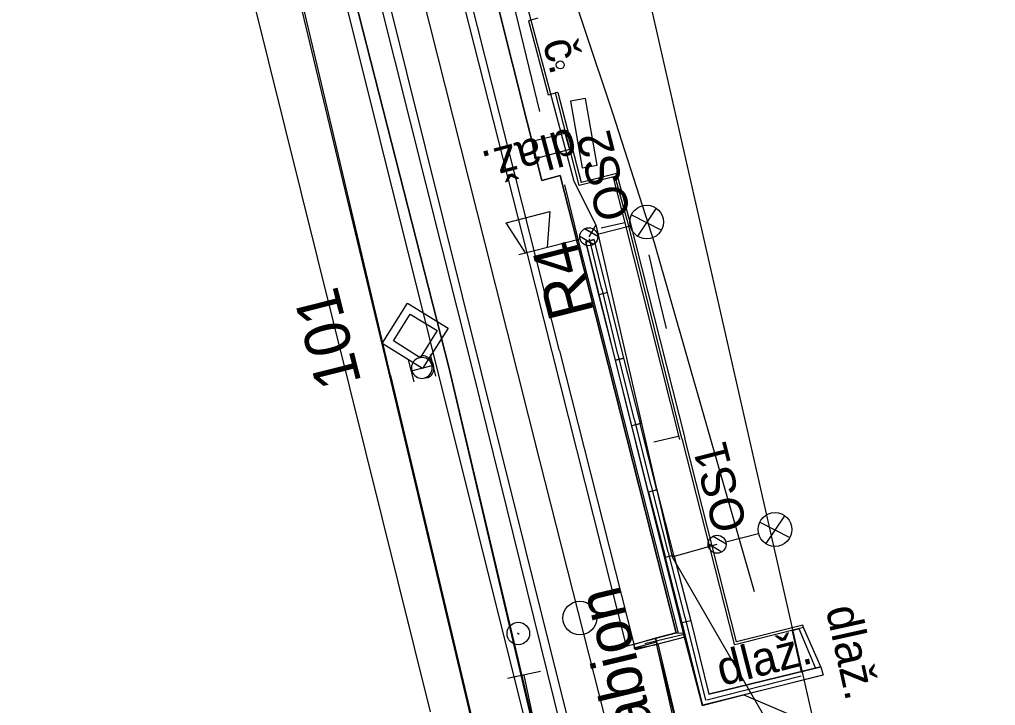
# Model space of a CAD drawing. Extents: x -754679 to -754173, y -1169241 to -1168288.
# Drawn here: x -754414.28 to -754371, y -1168944.54 to -1168914.1 of the extents above; entities that cross this region are included whole.
import ezdxf

# ---------------------------------------------------------------- set-up
doc = ezdxf.new("R2010")
doc.units = 0
for name, color, linetype in [('Vrstva 1', 7, 'Continuous'), ('Vrstva 11', 7, 'Continuous'), ('Vrstva 12', 7, 'Continuous'), ('Vrstva 13', 7, 'Continuous'), ('Vrstva 14', 7, 'Continuous'), ('Vrstva 16', 7, 'Continuous'), ('Vrstva 17', 7, 'Continuous'), ('Vrstva 23', 7, 'Continuous'), ('Vrstva 25', 7, 'Continuous'), ('Vrstva 31', 7, 'Continuous'), ('Vrstva 33', 7, 'Continuous'), ('Vrstva 4', 7, 'Continuous'), ('Vrstva 43', 7, 'Continuous'), ('Vrstva 49', 7, 'Continuous'), ('Vrstva 51', 7, 'Continuous'), ('Vrstva 53', 7, 'Continuous'), ('Vrstva 59', 7, 'Continuous'), ('Vrstva 6', 7, 'Continuous'), ('Vrstva 63', 7, 'Continuous'), ('Vrstva 7', 7, 'Continuous')]:
    doc.layers.add(name, color=color, linetype=linetype)

msp = doc.modelspace()

# ---------------------------------------------------------------- linework, layer by layer
at = {"layer": 'Vrstva 1'}
msp.add_lwpolyline([(-754384.656, -1168959.571), (-754385.936, -1168954.491), (-754386.734, -1168951.322), (-754387.865, -1168946.893), (-754387.928, -1168946.598), (-754389.016, -1168942.293), (-754391.2, -1168933.67), (-754393.647, -1168923.979), (-754396.084, -1168914.315), (-754398.294, -1168905.574)], dxfattribs=at)
at = {"layer": 'Vrstva 11'}
for p, q in [((-754396.779, -1168930.169), (-754397.024, -1168929.2)), ((-754395.81, -1168929.924), (-754396.055, -1168928.955)), ((-754396.902, -1168929.685), (-754395.932, -1168929.439))]:
    msp.add_line(p, q, dxfattribs=at)
at = {"layer": 'Vrstva 12'}
for p, q in [((-754396.521, -1168929.047), (-754396.519, -1168929.099)), ((-754395.985, -1168929.451), (-754395.912, -1168929.468)), ((-754396.315, -1168930.002), (-754396.285, -1168929.991))]:
    msp.add_line(p, q, dxfattribs=at)
for centre, major_axis, ratio, start_param, end_param in [((-754396.437, -1168929.555), (-0.102, 0.452), 0.999997, 6.240007, 10.999586), ((-754396.328, -1168929.506), (-0.199, 0.457), 0.826527, 2.759103, 6.267517), ((-754396.437, -1168929.555), (-0.102, 0.452), 0.999997, 3.184771, 6.240007)]:
    msp.add_ellipse(centre, major_axis=major_axis, ratio=ratio, start_param=start_param, end_param=end_param, dxfattribs=at)
at = {"layer": 'Vrstva 13'}
for p, q in [((-754388.795, -1168923.864), (-754389.165, -1168923.968)), ((-754388.582, -1168926.306), (-754389.165, -1168923.968)), ((-754389.165, -1168923.968), (-754389.161, -1168923.973)), ((-754389.161, -1168923.973), (-754388.795, -1168923.864)), ((-754389.161, -1168923.973), (-754386.419, -1168935.058)), ((-754388.209, -1168926.212), (-754388.795, -1168923.864)), ((-754388.795, -1168923.864), (-754388.795, -1168923.864)), ((-754388.209, -1168926.212), (-754388.582, -1168926.306)), ((-754388.207, -1168926.214), (-754388.582, -1168926.307)), ((-754388.582, -1168926.307), (-754388.582, -1168926.306)), ((-754387.853, -1168929.212), (-754388.582, -1168926.307)), ((-754388.207, -1168926.214), (-754388.209, -1168926.212)), ((-754387.475, -1168929.122), (-754388.207, -1168926.214)), ((-754387.475, -1168929.122), (-754387.853, -1168929.212)), ((-754387.853, -1168929.212), (-754387.481, -1168929.123)), ((-754387.123, -1168932.124), (-754387.853, -1168929.212)), ((-754387.853, -1168929.212), (-754387.853, -1168929.212)), ((-754387.481, -1168929.123), (-754387.475, -1168929.122)), ((-754386.748, -1168932.026), (-754387.481, -1168929.123)), ((-754386.748, -1168932.026), (-754387.123, -1168932.124)), ((-754387.122, -1168932.123), (-754387.123, -1168932.124)), ((-754386.75, -1168932.032), (-754387.122, -1168932.123)), ((-754386.387, -1168935.069), (-754387.122, -1168932.123)), ((-754386.75, -1168932.032), (-754386.748, -1168932.026)), ((-754386.01, -1168934.971), (-754386.75, -1168932.032)), ((-754386.419, -1168935.058), (-754384.844, -1168941.33)), ((-754386.009, -1168934.97), (-754386.387, -1168935.07)), ((-754386.01, -1168934.971), (-754386.387, -1168935.069)), ((-754386.387, -1168935.07), (-754386.387, -1168935.069)), ((-754386.387, -1168935.07), (-754385.634, -1168937.967)), ((-754386.009, -1168934.97), (-754386.01, -1168934.971)), ((-754385.256, -1168937.865), (-754386.009, -1168934.97)), ((-754385.256, -1168937.865), (-754385.634, -1168937.967)), ((-754385.256, -1168937.866), (-754385.631, -1168937.968)), ((-754385.256, -1168937.866), (-754385.256, -1168937.865)), ((-754385.256, -1168937.866), (-754384.511, -1168940.778)), ((-754385.631, -1168937.968), (-754385.634, -1168937.967)), ((-754384.889, -1168940.869), (-754385.631, -1168937.968)), ((-754384.51, -1168940.78), (-754384.892, -1168940.869)), ((-754383.981, -1168944.518), (-754384.892, -1168940.869)), ((-754384.892, -1168940.869), (-754384.889, -1168940.869)), ((-754384.511, -1168940.778), (-754384.889, -1168940.869)), ((-754384.51, -1168940.78), (-754384.511, -1168940.778)), ((-754384.511, -1168940.778), (-754383.714, -1168944.039)), ((-754384.51, -1168940.78), (-754383.714, -1168944.04)), ((-754384.844, -1168941.33), (-754384.011, -1168944.533)), ((-754386.071, -1168941.545), (-754387.015, -1168941.827)), ((-754386.027, -1168941.732), (-754386.979, -1168941.973)), ((-754386.008, -1168941.815), (-754386.071, -1168941.545)), ((-754386.027, -1168941.731), (-754386.027, -1168941.732)), ((-754386.007, -1168941.817), (-754386.027, -1168941.732)), ((-754385.963, -1168941.8), (-754384.759, -1168941.493)), ((-754384.759, -1168941.493), (-754384.006, -1168944.538)), ((-754386.97, -1168942.062), (-754387.015, -1168941.827)), ((-754386.96, -1168942.06), (-754386.979, -1168941.973)), ((-754386.008, -1168941.815), (-754386.97, -1168942.062)), ((-754386.023, -1168941.847), (-754385.963, -1168941.8)), ((-754385.064, -1168945.684), (-754386.023, -1168941.847)), ((-754386.008, -1168941.815), (-754386.007, -1168941.817)), ((-754385.032, -1168945.69), (-754385.963, -1168941.8)), ((-754383.714, -1168944.039), (-754378.74, -1168942.822)), ((-754378.748, -1168942.827), (-754383.714, -1168944.04)), ((-754378.748, -1168942.827), (-754378.74, -1168942.822)), ((-754378.748, -1168942.827), (-754378.643, -1168943.195)), ((-754378.65, -1168943.193), (-754384.011, -1168944.533)), ((-754378.643, -1168943.195), (-754383.981, -1168944.518)), ((-754378.643, -1168943.195), (-754378.65, -1168943.193)), ((-754383.714, -1168944.04), (-754383.714, -1168944.039)), ((-754383.981, -1168944.518), (-754384.011, -1168944.533))]:
    msp.add_line(p, q, dxfattribs=at)
for points in [[(-754386.027, -1168941.731), (-754386.982, -1168941.97), (-754386.979, -1168941.973)], [(-754386.007, -1168941.817), (-754386.96, -1168942.06), (-754386.97, -1168942.062)]]:
    msp.add_lwpolyline(points, dxfattribs=at)
at = {"layer": 'Vrstva 14'}
for p, q in [((-754391.113, -1168921.242), (-754393.063, -1168913.475)), ((-754390.299, -1168921.015), (-754391.113, -1168921.242)), ((-754389.528, -1168924.038), (-754390.299, -1168921.015)), ((-754385.162, -1168941.315), (-754389.528, -1168924.038)), ((-754387.375, -1168941.909), (-754385.162, -1168941.315))]:
    msp.add_line(p, q, dxfattribs=at)
msp.add_lwpolyline([(-754414.276, -1168835.483), (-754412.566, -1168842.248), (-754407.917, -1168860.63), (-754403.513, -1168878.067), (-754399.115, -1168895.474), (-754395.207, -1168910.943), (-754391.772, -1168924.511), (-754387.375, -1168941.909)], dxfattribs=at)
at = {"layer": 'Vrstva 16'}
for p, q in [((-754402.14, -1168902.474), (-754395.222, -1168929.578)), ((-754397.82, -1168929.888), (-754404.14, -1168903.209)), ((-754390.209, -1168950.962), (-754395.222, -1168929.578)), ((-754397.82, -1168929.888), (-754393.322, -1168948.872))]:
    msp.add_line(p, q, dxfattribs=at)
msp.add_lwpolyline([(-754391.54, -1168919.494), (-754390.097, -1168919.138), (-754389.895, -1168919.863), (-754391.413, -1168920.273), (-754391.54, -1168919.494)], dxfattribs=at)
at = {"layer": 'Vrstva 17'}
for p, q in [((-754384.808, -1168941.38), (-754386.547, -1168941.8)), ((-754379.619, -1168943.23), (-754383.796, -1168944.293))]:
    msp.add_line(p, q, dxfattribs=at)
msp.add_lwpolyline([(-754383.844, -1168944.301), (-754384.743, -1168940.667), (-754384.765, -1168940.627), (-754385.496, -1168937.745), (-754385.514, -1168937.714), (-754386.249, -1168934.81), (-754386.265, -1168934.776), (-754386.989, -1168931.888), (-754387.01, -1168931.853), (-754387.726, -1168928.979), (-754387.745, -1168928.942), (-754388.446, -1168926.057), (-754388.467, -1168926.021), (-754388.997, -1168923.827)], dxfattribs=at)
at = {"layer": 'Vrstva 23'}
msp.add_line((-754391.701, -1168914.153), (-754390.842, -1168917.432), dxfattribs=at)
for points in [[(-754381.681, -1168939.489), (-754386.122, -1168924.006), (-754387.953, -1168918.303), (-754395.607, -1168895.383), (-754402.869, -1168866.173)], [(-754393.344, -1168948.888), (-754397.546, -1168931.205), (-754401.742, -1168913.695), (-754408.583, -1168884.482)], [(-754386.365, -1168924.542), (-754385.996, -1168926.171), (-754385.598, -1168927.803)]]:
    msp.add_lwpolyline(points, dxfattribs=at)
msp.add_lwpolyline([(-754389.177, -1168917.603), (-754389.843, -1168917.719), (-754389.331, -1168920.671), (-754388.665, -1168920.555)], close=True, dxfattribs=at)
at = {"layer": 'Vrstva 25'}
for p, q in [((-754386.047, -1168922.471), (-754386.881, -1168923.707)), ((-754387.138, -1168922.762), (-754385.811, -1168923.442)), ((-754389.208, -1168923.377), (-754388.638, -1168923.717)), ((-754387.193, -1168923.27), (-754388.647, -1168923.637)), ((-754389.43, -1168923.71), (-754388.823, -1168924.072)), ((-754380.356, -1168936.113), (-754381.19, -1168937.349)), ((-754381.448, -1168936.405), (-754380.12, -1168937.083)), ((-754383.517, -1168937.022), (-754382.947, -1168937.361)), ((-754381.502, -1168936.913), (-754382.956, -1168937.281)), ((-754383.739, -1168937.354), (-754383.132, -1168937.716))]:
    msp.add_line(p, q, dxfattribs=at)
for points in [[(-754392.606, -1168910.34), (-754389.7, -1168921.276), (-754388.719, -1168923.201), (-754389.035, -1168923.735)], [(-754388.719, -1168923.201), (-754385.337, -1168937.932), (-754383.344, -1168937.379)], [(-754385.337, -1168937.932), (-754380.924, -1168945.594), (-754378.67, -1168951.057), (-754378.525, -1168951.376)]]:
    msp.add_lwpolyline(points, dxfattribs=at)
for centre, radius in [((-754386.468, -1168923.084), 0.749), ((-754389.035, -1168923.735), 0.4), ((-754380.777, -1168936.726), 0.749), ((-754383.344, -1168937.379), 0.4)]:
    msp.add_circle(centre, radius, dxfattribs=at)
at = {"layer": 'Vrstva 31'}
for points in [[(-754392.606, -1168910.34), (-754389.7, -1168921.276), (-754388.719, -1168923.201), (-754389.035, -1168923.735)], [(-754388.719, -1168923.201), (-754385.337, -1168937.932), (-754380.924, -1168945.594), (-754378.67, -1168951.057), (-754378.525, -1168951.376)]]:
    msp.add_lwpolyline(points, dxfattribs=at)
at = {"layer": 'Vrstva 33'}
for p, q in [((-754388.637, -1168923.732), (-754389.222, -1168923.383)), ((-754392.134, -1168924.517), (-754389.423, -1168923.833)), ((-754388.834, -1168924.08), (-754389.432, -1168923.724))]:
    msp.add_line(p, q, dxfattribs=at)
msp.add_lwpolyline([(-754391.843, -1168924.444), (-754392.695, -1168923.112), (-754390.756, -1168922.622), (-754390.873, -1168924.199)], dxfattribs=at)
msp.add_circle((-754389.035, -1168923.735), 0.401, dxfattribs=at)
at = {"layer": 'Vrstva 4'}
for p, q in [((-754390.328, -1168928.8), (-754397.327, -1168901.139)), ((-754401.081, -1168902.211), (-754394.179, -1168929.708)), ((-754393.809, -1168929.698), (-754400.667, -1168902.072)), ((-754395.222, -1168929.578), (-754402.14, -1168902.474)), ((-754390.328, -1168928.8), (-754387.041, -1168941.818)), ((-754395.222, -1168929.578), (-754390.121, -1168951.135)), ((-754394.179, -1168929.708), (-754388.744, -1168951.72)), ((-754388.295, -1168951.767), (-754393.809, -1168929.698)), ((-754387.041, -1168941.818), (-754387.022, -1168942.028)), ((-754386.014, -1168941.847), (-754387.022, -1168942.028)), ((-754385.154, -1168945.699), (-754386.014, -1168941.847))]:
    msp.add_line(p, q, dxfattribs=at)
at = {"layer": 'Vrstva 43'}
msp.add_line((-754392.405, -1168913.302), (-754391.226, -1168918.175), dxfattribs=at)
for points in [[(-754390.117, -1168921.433), (-754389.474, -1168924.019), (-754385.071, -1168941.331)], [(-754387.959, -1168921.11), (-754387.458, -1168922.996), (-754385.012, -1168932.727)], [(-754388.48, -1168923.343), (-754387.515, -1168923.117), (-754387.432, -1168923.098)], [(-754386.146, -1168932.839), (-754385.129, -1168932.595), (-754385.05, -1168932.576)]]:
    msp.add_lwpolyline(points, dxfattribs=at)
at = {"layer": 'Vrstva 49'}
msp.add_lwpolyline([(-754384.006, -1168944.538), (-754382.158, -1168944.067), (-754378.6, -1168945.58), (-754377.58, -1168949.01), (-754375.672, -1168950.079), (-754373.052, -1168951.324)], dxfattribs=at)
at = {"layer": 'Vrstva 51'}
for p, q in [((-754391.3, -1168914.039), (-754391.701, -1168914.153)), ((-754391.701, -1168914.153), (-754390.842, -1168917.432)), ((-754390.842, -1168917.432), (-754390.515, -1168917.354)), ((-754390.409, -1168917.33), (-754390.515, -1168917.354)), ((-754389.458, -1168921.46), (-754390.515, -1168917.354)), ((-754390.409, -1168917.33), (-754389.375, -1168921.333)), ((-754387.792, -1168920.929), (-754389.375, -1168921.333)), ((-754387.227, -1168922.984), (-754387.792, -1168920.929)), ((-754387.86, -1168921.064), (-754389.458, -1168921.46)), ((-754387.326, -1168923.005), (-754387.86, -1168921.064)), ((-754387.318, -1168923.01), (-754387.326, -1168923.005)), ((-754384.905, -1168932.683), (-754387.318, -1168923.01)), ((-754387.227, -1168922.984), (-754384.774, -1168932.673)), ((-754382.483, -1168941.706), (-754384.774, -1168932.673)), ((-754385.162, -1168941.315), (-754386.071, -1168941.545)), ((-754385.162, -1168941.315), (-754384.844, -1168941.33)), ((-754379.545, -1168940.978), (-754382.483, -1168941.706)), ((-754379.515, -1168941.074), (-754379.545, -1168940.978)), ((-754378.74, -1168942.822), (-754379.515, -1168941.074)), ((-754386.071, -1168941.545), (-754386.008, -1168941.815))]:
    msp.add_line(p, q, dxfattribs=at)
for points in [[(-754412.047, -1168834.907), (-754410.208, -1168842.187), (-754405.698, -1168860.083), (-754401.304, -1168877.422), (-754396.888, -1168895.004), (-754392.927, -1168910.532), (-754392.287, -1168913.272), (-754393.063, -1168913.475), (-754391.113, -1168921.242), (-754390.299, -1168921.015), (-754389.528, -1168924.038), (-754385.162, -1168941.315)], [(-754384.905, -1168932.683), (-754382.598, -1168941.756), (-754382.574, -1168941.851)], [(-754379.515, -1168941.074), (-754382.438, -1168941.816), (-754382.574, -1168941.851)], [(-754379.618, -1168943.048), (-754378.986, -1168942.865), (-754379.706, -1168941.132), (-754380.023, -1168941.222), (-754379.618, -1168943.048)]]:
    msp.add_lwpolyline(points, dxfattribs=at)
at = {"layer": 'Vrstva 53'}
for p, q in [((-754396.56, -1168868.29), (-754379.05, -1168945.33)), ((-754396.05, -1168944.82), (-754406.43, -1168903.09))]:
    msp.add_line(p, q, dxfattribs=at)
at = {"layer": 'Vrstva 59'}
msp.add_circle((-754390.301, -1168916.112), 0.175, dxfattribs=at)
at = {"layer": 'Vrstva 6'}
for points in [[(-754396.401, -1168929.589), (-754398.19, -1168928.47), (-754397.068, -1168926.676), (-754395.276, -1168927.791), (-754396.401, -1168929.589)], [(-754397.691, -1168928.355), (-754396.955, -1168927.167), (-754395.763, -1168927.903), (-754396.513, -1168929.102), (-754397.691, -1168928.355)]]:
    msp.add_lwpolyline(points, dxfattribs=at)
at = {"layer": 'Vrstva 63'}
msp.add_lwpolyline([(-754409.148, -1168875.914), (-754380.947, -1168989.007), (-754335.988, -1169164.84)], dxfattribs=at)
at = {"layer": 'Vrstva 7'}
for p, q in [((-754392.201, -1168941.318), (-754392.117, -1168941.372)), ((-754391.175, -1168943.032), (-754392.643, -1168943.338))]:
    msp.add_line(p, q, dxfattribs=at)
msp.add_lwpolyline([(-754391.909, -1168943.185), (-754391.296, -1168946.122), (-754393.009, -1168946.479), (-754392.499, -1168948.927), (-754389.072, -1168948.212), (-754389.583, -1168945.764), (-754391.296, -1168946.122)], dxfattribs=at)
for centre, radius in [((-754389.431, -1168940.654), 0.75), ((-754392.159, -1168941.345), 0.5)]:
    msp.add_circle(centre, radius, dxfattribs=at)

# ---------------------------------------------------------------- texts
at = {"layer": 'Vrstva 11'}
msp.add_text('101', height=2, rotation=104.1967, dxfattribs=at).set_placement((-754399.109, -1168930.195))
at = {"layer": 'Vrstva 13'}
msp.add_text('gabion', height=2, rotation=103.4595, dxfattribs=at).set_placement((-754385.81, -1168946.939))
at = {"layer": 'Vrstva 16'}
msp.add_text('dlaž.', height=1.5, rotation=195.1145, dxfattribs=at).set_placement((-754389.798, -1168918.889))
at = {"layer": 'Vrstva 23'}
msp.add_text('č.', height=1.5, rotation=284.6799, dxfattribs=at).set_placement((-754391.088, -1168915.114))
at = {"layer": 'Vrstva 25'}
for s, rotation, p in [('OS2', 104.1711, (-754387.15, -1168922.805)), ('OS1', 104.2128, (-754382.002, -1168936.617))]:
    msp.add_text(s, height=1.5, rotation=rotation, dxfattribs=at).set_placement(p)
at = {"layer": 'Vrstva 33'}
msp.add_text('R4', height=2, rotation=104.1711, dxfattribs=at).set_placement((-754388.803, -1168927.09))
at = {"layer": 'Vrstva 51'}
for rotation, p in [(282.5055, (-754378.53, -1168940.254)), (14.2436, (-754383.143, -1168943.676))]:
    msp.add_text('dlaž.', height=1.5, rotation=rotation, dxfattribs=at).set_placement(p)

doc.saveas('drawing.dxf')
